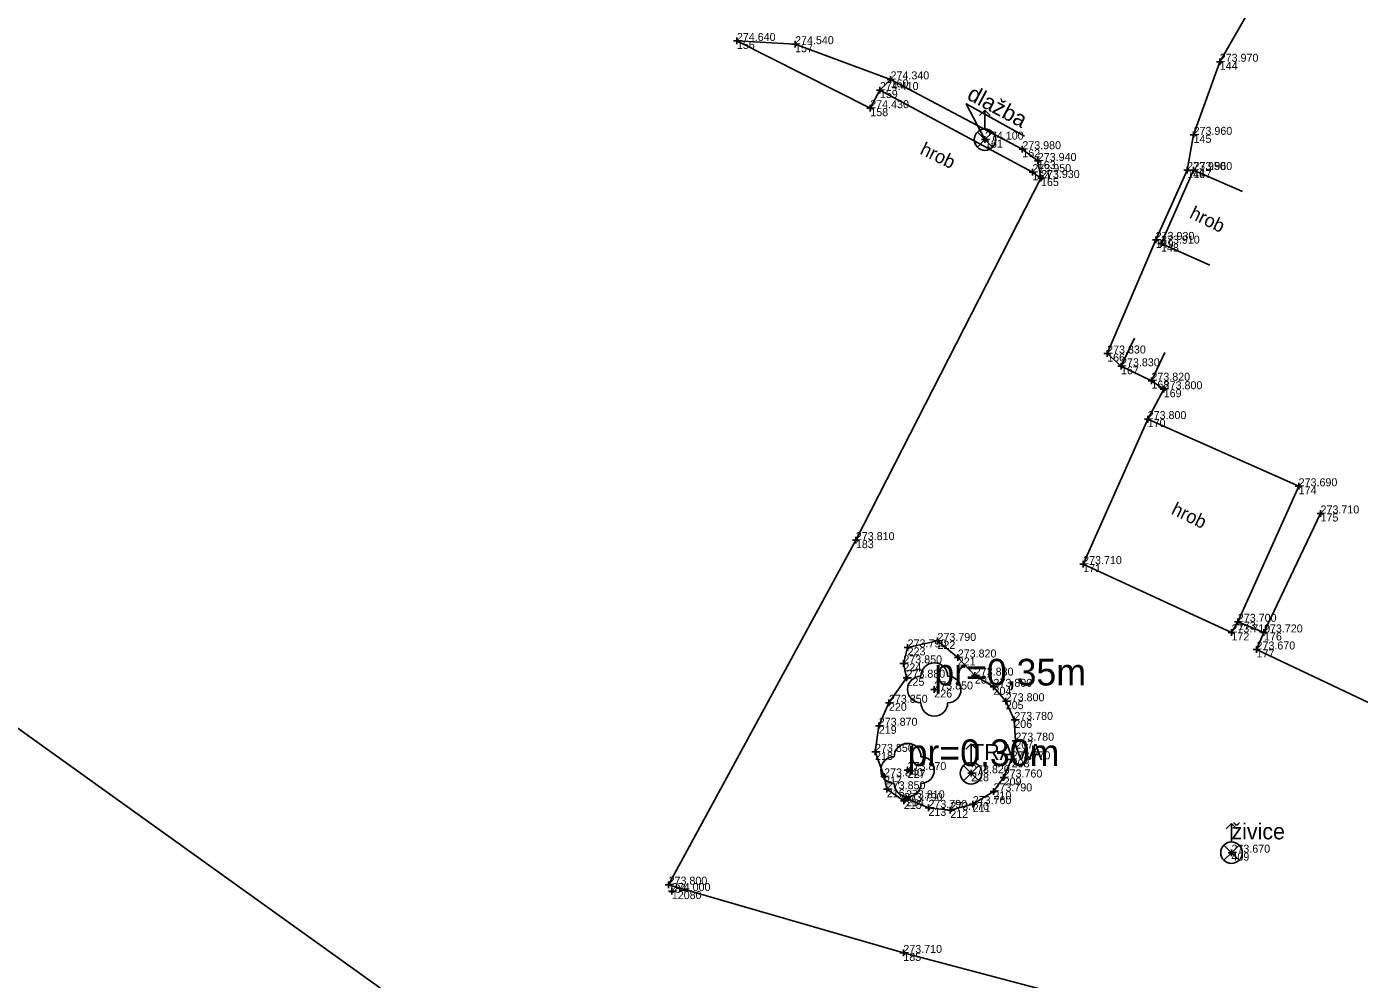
# Model space of a CAD drawing. Extents: x -776606 to -776076, y -974328 to -973875.
# Drawn here: x -776421.12 to -776396.14, y -974197.28 to -974179.42 of the extents above; entities that cross this region are included whole.
import ezdxf

# ---------------------------------------------------------------- set-up
doc = ezdxf.new("R2010")
doc.units = 0
for name, color, linetype in [('Body polohopisu', 7, 'Continuous'), ('Doplňkové značky', 7, 'Continuous'), ('Doplňující texty', 7, 'Continuous'), ('Hranice parcel', 7, 'Continuous'), ('Nezařazené objekty', 7, 'Continuous'), ('Ploty_opěrné zdi', 7, 'Continuous'), ('Rozhraní ploch', 7, 'Continuous'), ('Stromy_porost', 7, 'Continuous'), ('Výšky bodů', 7, 'Continuous'), ('Čísla bodů', 7, 'Continuous')]:
    doc.layers.add(name, color=color, linetype=linetype)

msp = doc.modelspace()

# ---------------------------------------------------------------- linework, layer by layer
at = {"layer": 'Body polohopisu'}
for p, q in [((-776407.81, -974179.69), (-776407.873, -974179.69)), ((-776407.81, -974179.69), (-776407.81, -974179.628)), ((-776407.81, -974179.69), (-776407.748, -974179.69)), ((-776407.81, -974179.69), (-776407.81, -974179.753)), ((-776406.72, -974179.75), (-776406.782, -974179.75)), ((-776406.72, -974179.75), (-776406.72, -974179.688)), ((-776406.72, -974179.75), (-776406.657, -974179.75)), ((-776406.72, -974179.75), (-776406.72, -974179.812)), ((-776398.76, -974180.08), (-776398.823, -974180.08)), ((-776398.76, -974180.08), (-776398.76, -974180.018)), ((-776398.76, -974180.08), (-776398.698, -974180.08)), ((-776398.76, -974180.08), (-776398.76, -974180.143)), ((-776405.13, -974180.61), (-776405.13, -974180.547)), ((-776404.93, -974180.41), (-776404.993, -974180.41)), ((-776404.93, -974180.41), (-776404.93, -974180.348)), ((-776404.93, -974180.41), (-776404.868, -974180.41)), ((-776404.93, -974180.41), (-776404.93, -974180.473)), ((-776405.13, -974180.61), (-776405.193, -974180.61)), ((-776405.13, -974180.61), (-776405.068, -974180.61)), ((-776405.13, -974180.61), (-776405.13, -974180.672)), ((-776405.31, -974180.95), (-776405.373, -974180.95)), ((-776405.31, -974180.95), (-776405.31, -974180.888)), ((-776405.31, -974180.95), (-776405.248, -974180.95)), ((-776405.31, -974180.95), (-776405.31, -974181.013)), ((-776403.16, -974181.54), (-776403.223, -974181.54)), ((-776403.16, -974181.54), (-776403.16, -974181.478)), ((-776403.16, -974181.54), (-776403.098, -974181.54)), ((-776403.16, -974181.54), (-776403.16, -974181.603)), ((-776399.25, -974181.45), (-776399.312, -974181.45)), ((-776399.25, -974181.45), (-776399.25, -974181.388)), ((-776399.25, -974181.45), (-776399.188, -974181.45)), ((-776399.25, -974181.45), (-776399.25, -974181.513)), ((-776402.46, -974181.72), (-776402.522, -974181.72)), ((-776402.46, -974181.72), (-776402.46, -974181.657)), ((-776402.46, -974181.72), (-776402.397, -974181.72)), ((-776402.46, -974181.72), (-776402.46, -974181.782)), ((-776402.17, -974181.94), (-776402.233, -974181.94)), ((-776402.17, -974181.94), (-776402.17, -974181.878)), ((-776402.17, -974181.94), (-776402.108, -974181.94)), ((-776402.17, -974181.94), (-776402.17, -974182.003)), ((-776399.37, -974182.11), (-776399.37, -974182.047)), ((-776399.25, -974182.11), (-776399.25, -974182.047)), ((-776402.27, -974182.15), (-776402.333, -974182.15)), ((-776402.27, -974182.15), (-776402.27, -974182.088)), ((-776402.27, -974182.15), (-776402.208, -974182.15)), ((-776402.27, -974182.15), (-776402.27, -974182.213)), ((-776402.11, -974182.26), (-776402.172, -974182.26)), ((-776402.11, -974182.26), (-776402.11, -974182.198)), ((-776402.11, -974182.26), (-776402.047, -974182.26)), ((-776402.11, -974182.26), (-776402.11, -974182.323)), ((-776399.37, -974182.11), (-776399.432, -974182.11)), ((-776399.37, -974182.11), (-776399.307, -974182.11)), ((-776399.37, -974182.11), (-776399.37, -974182.172)), ((-776399.25, -974182.11), (-776399.312, -974182.11)), ((-776399.25, -974182.11), (-776399.188, -974182.11)), ((-776399.25, -974182.11), (-776399.25, -974182.172)), ((-776399.96, -974183.42), (-776400.022, -974183.42)), ((-776399.96, -974183.42), (-776399.96, -974183.358)), ((-776399.96, -974183.42), (-776399.897, -974183.42)), ((-776399.96, -974183.42), (-776399.96, -974183.483)), ((-776399.86, -974183.49), (-776399.922, -974183.49)), ((-776399.86, -974183.49), (-776399.86, -974183.427)), ((-776399.86, -974183.49), (-776399.797, -974183.49)), ((-776399.86, -974183.49), (-776399.86, -974183.552)), ((-776400.87, -974185.55), (-776400.932, -974185.55)), ((-776400.87, -974185.55), (-776400.87, -974185.488)), ((-776400.87, -974185.55), (-776400.807, -974185.55)), ((-776400.87, -974185.55), (-776400.87, -974185.613)), ((-776400.61, -974185.79), (-776400.672, -974185.79)), ((-776400.61, -974185.79), (-776400.61, -974185.728)), ((-776400.61, -974185.79), (-776400.547, -974185.79)), ((-776400.61, -974185.79), (-776400.61, -974185.853)), ((-776400.04, -974186.06), (-776400.103, -974186.06)), ((-776400.04, -974186.06), (-776400.04, -974185.998)), ((-776400.04, -974186.06), (-776399.978, -974186.06)), ((-776400.04, -974186.06), (-776400.04, -974186.123)), ((-776399.81, -974186.22), (-776399.873, -974186.22)), ((-776399.81, -974186.22), (-776399.81, -974186.157)), ((-776399.81, -974186.22), (-776399.748, -974186.22)), ((-776399.81, -974186.22), (-776399.81, -974186.282)), ((-776400.11, -974186.78), (-776400.172, -974186.78)), ((-776400.11, -974186.78), (-776400.11, -974186.718)), ((-776400.11, -974186.78), (-776400.047, -974186.78)), ((-776400.11, -974186.78), (-776400.11, -974186.843)), ((-776397.28, -974188.04), (-776397.343, -974188.04)), ((-776397.28, -974188.04), (-776397.28, -974187.978)), ((-776397.28, -974188.04), (-776397.218, -974188.04)), ((-776397.28, -974188.04), (-776397.28, -974188.103)), ((-776396.87, -974188.55), (-776396.932, -974188.55)), ((-776396.87, -974188.55), (-776396.87, -974188.488)), ((-776396.87, -974188.55), (-776396.807, -974188.55)), ((-776396.87, -974188.55), (-776396.87, -974188.613)), ((-776405.58, -974189.05), (-776405.642, -974189.05)), ((-776405.58, -974189.05), (-776405.58, -974188.988)), ((-776405.58, -974189.05), (-776405.517, -974189.05)), ((-776405.58, -974189.05), (-776405.58, -974189.113)), ((-776401.32, -974189.5), (-776401.383, -974189.5)), ((-776401.32, -974189.5), (-776401.32, -974189.438)), ((-776401.32, -974189.5), (-776401.258, -974189.5)), ((-776401.32, -974189.5), (-776401.32, -974189.562)), ((-776398.42, -974190.58), (-776398.42, -974190.518)), ((-776398.54, -974190.78), (-776398.603, -974190.78)), ((-776398.54, -974190.78), (-776398.54, -974190.718)), ((-776398.54, -974190.78), (-776398.478, -974190.78)), ((-776398.54, -974190.78), (-776398.54, -974190.843)), ((-776398.42, -974190.58), (-776398.483, -974190.58)), ((-776398.42, -974190.58), (-776398.358, -974190.58)), ((-776398.42, -974190.58), (-776398.42, -974190.643)), ((-776397.93, -974190.78), (-776397.993, -974190.78)), ((-776397.93, -974190.78), (-776397.93, -974190.718)), ((-776397.93, -974190.78), (-776397.868, -974190.78)), ((-776397.93, -974190.78), (-776397.93, -974190.843)), ((-776404.61, -974191.06), (-776404.672, -974191.06)), ((-776404.61, -974191.06), (-776404.61, -974190.998)), ((-776404.61, -974191.06), (-776404.547, -974191.06)), ((-776404.61, -974191.06), (-776404.61, -974191.123)), ((-776404.05, -974190.94), (-776404.113, -974190.94)), ((-776404.05, -974190.94), (-776404.05, -974190.878)), ((-776404.05, -974190.94), (-776403.988, -974190.94)), ((-776404.05, -974190.94), (-776404.05, -974191.003)), ((-776398.07, -974191.1), (-776398.07, -974191.037)), ((-776404.69, -974191.36), (-776404.69, -974191.297)), ((-776403.67, -974191.25), (-776403.733, -974191.25)), ((-776403.67, -974191.25), (-776403.67, -974191.188)), ((-776403.67, -974191.25), (-776403.608, -974191.25)), ((-776403.67, -974191.25), (-776403.67, -974191.312)), ((-776398.07, -974191.1), (-776398.133, -974191.1)), ((-776398.07, -974191.1), (-776398.008, -974191.1)), ((-776398.07, -974191.1), (-776398.07, -974191.162)), ((-776404.69, -974191.36), (-776404.753, -974191.36)), ((-776404.69, -974191.36), (-776404.628, -974191.36)), ((-776404.69, -974191.36), (-776404.69, -974191.422)), ((-776404.63, -974191.63), (-776404.63, -974191.568)), ((-776403.35, -974191.59), (-776403.35, -974191.527)), ((-776404.63, -974191.63), (-776404.693, -974191.63)), ((-776404.63, -974191.63), (-776404.568, -974191.63)), ((-776404.63, -974191.63), (-776404.63, -974191.693)), ((-776404.11, -974191.85), (-776404.11, -974191.787)), ((-776403.35, -974191.59), (-776403.412, -974191.59)), ((-776403.35, -974191.59), (-776403.287, -974191.59)), ((-776403.35, -974191.59), (-776403.35, -974191.652)), ((-776403, -974191.8), (-776403.062, -974191.8)), ((-776403, -974191.8), (-776403, -974191.738)), ((-776403, -974191.8), (-776402.938, -974191.8)), ((-776403, -974191.8), (-776403, -974191.863)), ((-776404.96, -974192.1), (-776404.96, -974192.037)), ((-776404.11, -974191.85), (-776404.172, -974191.85)), ((-776404.11, -974191.85), (-776404.047, -974191.85)), ((-776404.11, -974191.85), (-776404.11, -974191.912)), ((-776402.77, -974192.07), (-776402.833, -974192.07)), ((-776402.77, -974192.07), (-776402.77, -974192.008)), ((-776402.77, -974192.07), (-776402.708, -974192.07)), ((-776402.77, -974192.07), (-776402.77, -974192.133)), ((-776404.96, -974192.1), (-776405.022, -974192.1)), ((-776404.96, -974192.1), (-776404.897, -974192.1)), ((-776404.96, -974192.1), (-776404.96, -974192.162)), ((-776405.15, -974192.53), (-776405.213, -974192.53)), ((-776405.15, -974192.53), (-776405.15, -974192.468)), ((-776405.15, -974192.53), (-776405.088, -974192.53)), ((-776405.15, -974192.53), (-776405.15, -974192.593)), ((-776402.61, -974192.42), (-776402.672, -974192.42)), ((-776402.61, -974192.42), (-776402.61, -974192.358)), ((-776402.61, -974192.42), (-776402.547, -974192.42)), ((-776402.61, -974192.42), (-776402.61, -974192.483)), ((-776402.59, -974192.81), (-776402.652, -974192.81)), ((-776402.59, -974192.81), (-776402.59, -974192.748)), ((-776402.59, -974192.81), (-776402.527, -974192.81)), ((-776402.59, -974192.81), (-776402.59, -974192.873)), ((-776405.22, -974193.02), (-776405.282, -974193.02)), ((-776405.22, -974193.02), (-776405.22, -974192.958)), ((-776405.22, -974193.02), (-776405.157, -974193.02)), ((-776405.22, -974193.02), (-776405.22, -974193.083)), ((-776404.61, -974193.36), (-776404.61, -974193.297)), ((-776402.66, -974193.16), (-776402.723, -974193.16)), ((-776402.66, -974193.16), (-776402.66, -974193.098)), ((-776402.66, -974193.16), (-776402.598, -974193.16)), ((-776402.66, -974193.16), (-776402.66, -974193.223)), ((-776405.05, -974193.48), (-776405.113, -974193.48)), ((-776405.05, -974193.48), (-776405.05, -974193.417)), ((-776405.05, -974193.48), (-776404.988, -974193.48)), ((-776405.05, -974193.48), (-776405.05, -974193.542)), ((-776404.61, -974193.36), (-776404.672, -974193.36)), ((-776404.61, -974193.36), (-776404.547, -974193.36)), ((-776404.61, -974193.36), (-776404.61, -974193.422)), ((-776403.42, -974193.42), (-776403.483, -974193.42)), ((-776403.42, -974193.42), (-776403.42, -974193.358)), ((-776403.42, -974193.42), (-776403.358, -974193.42)), ((-776403.42, -974193.42), (-776403.42, -974193.483)), ((-776402.81, -974193.5), (-776402.873, -974193.5)), ((-776402.81, -974193.5), (-776402.81, -974193.438)), ((-776402.81, -974193.5), (-776402.748, -974193.5)), ((-776402.81, -974193.5), (-776402.81, -974193.562)), ((-776405, -974193.72), (-776405.062, -974193.72)), ((-776405, -974193.72), (-776405, -974193.657)), ((-776405, -974193.72), (-776404.938, -974193.72)), ((-776405, -974193.72), (-776405, -974193.782)), ((-776403, -974193.76), (-776403.062, -974193.76)), ((-776403, -974193.76), (-776403, -974193.698)), ((-776403, -974193.76), (-776402.938, -974193.76)), ((-776403, -974193.76), (-776403, -974193.823)), ((-776404.68, -974193.94), (-776404.743, -974193.94)), ((-776404.64, -974193.89), (-776404.703, -974193.89)), ((-776404.68, -974193.94), (-776404.68, -974193.878)), ((-776404.68, -974193.94), (-776404.618, -974193.94)), ((-776404.68, -974193.94), (-776404.68, -974194.003)), ((-776404.64, -974193.89), (-776404.64, -974193.828)), ((-776404.64, -974193.89), (-776404.578, -974193.89)), ((-776404.64, -974193.89), (-776404.64, -974193.953)), ((-776404.22, -974194.07), (-776404.282, -974194.07)), ((-776404.22, -974194.07), (-776404.22, -974194.008)), ((-776404.22, -974194.07), (-776404.157, -974194.07)), ((-776404.22, -974194.07), (-776404.22, -974194.133)), ((-776403.81, -974194.11), (-776403.81, -974194.047)), ((-776403.39, -974194), (-776403.453, -974194)), ((-776403.39, -974194), (-776403.39, -974193.938)), ((-776403.39, -974194), (-776403.328, -974194)), ((-776403.39, -974194), (-776403.39, -974194.062)), ((-776403.81, -974194.11), (-776403.873, -974194.11)), ((-776403.81, -974194.11), (-776403.748, -974194.11)), ((-776403.81, -974194.11), (-776403.81, -974194.172)), ((-776398.54, -974194.91), (-776398.603, -974194.91)), ((-776398.54, -974194.91), (-776398.54, -974194.848)), ((-776398.54, -974194.91), (-776398.478, -974194.91)), ((-776398.54, -974194.91), (-776398.54, -974194.973)), ((-776409.09, -974195.51), (-776409.152, -974195.51)), ((-776409.09, -974195.51), (-776409.09, -974195.448)), ((-776409.09, -974195.51), (-776409.027, -974195.51)), ((-776409.09, -974195.51), (-776409.09, -974195.573)), ((-776409.03, -974195.63), (-776409.03, -974195.568)), ((-776409.03, -974195.63), (-776409.093, -974195.63)), ((-776409.03, -974195.63), (-776408.968, -974195.63)), ((-776409.03, -974195.63), (-776409.03, -974195.693)), ((-776404.69, -974196.79), (-776404.753, -974196.79)), ((-776404.69, -974196.79), (-776404.69, -974196.728)), ((-776404.69, -974196.79), (-776404.628, -974196.79)), ((-776404.69, -974196.79), (-776404.69, -974196.853))]:
    msp.add_line(p, q, dxfattribs=at)
at = {"layer": 'Doplňkové značky'}
for p, q in [((-776403.16, -974180.99), (-776403.26, -974181.09)), ((-776403.16, -974181.338), (-776403.16, -974180.99)), ((-776403.16, -974180.99), (-776403.06, -974181.09)), ((-776403.16, -974181.54), (-776403.302, -974181.397)), ((-776403.16, -974181.54), (-776403.302, -974181.682)), ((-776403.16, -974181.54), (-776403.017, -974181.397)), ((-776403.16, -974181.54), (-776403.16, -974181.54)), ((-776403.16, -974181.54), (-776403.017, -974181.682)), ((-776403.42, -974192.87), (-776403.52, -974192.97)), ((-776403.42, -974193.218), (-776403.42, -974192.87)), ((-776403.42, -974192.87), (-776403.32, -974192.97)), ((-776403.42, -974193.42), (-776403.562, -974193.277)), ((-776403.42, -974193.42), (-776403.277, -974193.277)), ((-776403.42, -974193.42), (-776403.562, -974193.562)), ((-776403.42, -974193.42), (-776403.42, -974193.42)), ((-776403.42, -974193.42), (-776403.277, -974193.562)), ((-776398.54, -974194.36), (-776398.64, -974194.46)), ((-776398.54, -974194.708), (-776398.54, -974194.36)), ((-776398.54, -974194.36), (-776398.44, -974194.46)), ((-776398.54, -974194.91), (-776398.682, -974194.768)), ((-776398.54, -974194.91), (-776398.397, -974194.768)), ((-776398.54, -974194.91), (-776398.682, -974195.052)), ((-776398.54, -974194.91), (-776398.54, -974194.91)), ((-776398.54, -974194.91), (-776398.397, -974195.052))]:
    msp.add_line(p, q, dxfattribs=at)
for centre in [(-776403.16, -974181.54), (-776403.42, -974193.42), (-776398.54, -974194.91)]:
    msp.add_circle(centre, 0.202, dxfattribs=at)
at = {"layer": 'Doplňující texty'}
msp.add_lwpolyline([(-776403.16, -974181.54), (-776403.51, -974180.868), (-776402.419, -974181.473)], dxfattribs=at)
at = {"layer": 'Hranice parcel'}
msp.add_line((-776424.22, -974190.48), (-776414.02, -974197.79), dxfattribs=at)
at = {"layer": 'Nezařazené objekty'}
for points in [[(-776405.05, -974193.48), (-776405.22, -974193.02), (-776405.15, -974192.53), (-776404.96, -974192.1), (-776404.63, -974191.63)], [(-776403.35, -974191.59), (-776403, -974191.8), (-776402.77, -974192.07), (-776402.61, -974192.42), (-776402.59, -974192.81), (-776402.66, -974193.16), (-776402.81, -974193.5), (-776403, -974193.76), (-776403.39, -974194), (-776403.81, -974194.11), (-776404.22, -974194.07), (-776404.64, -974193.89), (-776404.68, -974193.94), (-776405, -974193.72)]]:
    msp.add_lwpolyline(points, dxfattribs=at)
at = {"layer": 'Ploty_opěrné zdi'}
msp.add_lwpolyline([(-776405.31, -974180.95), (-776405.13, -974180.61), (-776402.27, -974182.15)], dxfattribs=at)
at = {"layer": 'Rozhraní ploch'}
for points in [[(-776397.41, -974177.93), (-776398.03, -974178.81), (-776398.76, -974180.08), (-776399.25, -974181.45), (-776399.37, -974182.11), (-776399.96, -974183.42), (-776400.87, -974185.55), (-776400.61, -974185.79)], [(-776407.81, -974179.69), (-776406.72, -974179.75), (-776404.93, -974180.41), (-776402.46, -974181.72), (-776402.17, -974181.94), (-776402.11, -974182.26)], [(-776407.81, -974179.69), (-776405.31, -974180.95)], [(-776405.13, -974180.61), (-776404.93, -974180.41)], [(-776402.27, -974182.15), (-776402.11, -974182.26), (-776405.58, -974189.05), (-776409.09, -974195.51), (-776404.69, -974196.79), (-776400.93, -974197.78), (-776396.03, -974199.17), (-776396.07, -974199.37), (-776395.22, -974199.6), (-776395.17, -974199.4), (-776393.77, -974199.81), (-776393.73, -974199.63), (-776391.65, -974200.17), (-776391.69, -974200.35), (-776390.84, -974200.57), (-776390.78, -974200.41), (-776385.82, -974201.79), (-776382.94, -974202.63), (-776383.306, -974203.936)], [(-776398.335, -974182.514), (-776399.25, -974182.11), (-776399.86, -974183.49), (-776398.945, -974183.894)], [(-776400.359, -974185.26), (-776400.61, -974185.79), (-776400.04, -974186.06), (-776399.789, -974185.53)], [(-776400.04, -974186.06), (-776399.81, -974186.22), (-776400.11, -974186.78)], [(-776397.28, -974188.04), (-776400.11, -974186.78), (-776401.32, -974189.5), (-776398.54, -974190.78), (-776398.42, -974190.58), (-776397.28, -974188.04)], [(-776396.87, -974188.55), (-776397.93, -974190.78), (-776398.07, -974191.1), (-776394.63, -974192.73), (-776391.17, -974194.38), (-776387.73, -974195.98), (-776387.69, -974195.93), (-776384.31, -974197.58), (-776380.77, -974199.14), (-776379.53, -974196.48)], [(-776398.42, -974190.58), (-776397.93, -974190.78)], [(-776403.35, -974191.59), (-776403.67, -974191.25), (-776404.05, -974190.94), (-776404.61, -974191.06), (-776404.69, -974191.36), (-776404.63, -974191.63)], [(-776405, -974193.72), (-776405.05, -974193.48)]]:
    msp.add_lwpolyline(points, dxfattribs=at)
at = {"layer": 'Stromy_porost'}
for centre in [(-776404.11, -974191.85), (-776404.61, -974193.36)]:
    msp.add_circle(centre, 0.00025, dxfattribs=at)
for centre, start, end in [((-776404.11, -974191.6), 0, 180), ((-776404.36, -974191.85), 90, 270), ((-776403.86, -974191.85), 270, 90), ((-776404.11, -974192.1), 180, 360), ((-776404.61, -974193.11), 0, 180), ((-776404.86, -974193.36), 90, 270), ((-776404.36, -974193.36), 270, 90), ((-776404.61, -974193.61), 180, 360)]:
    msp.add_arc(centre, 0.25, start, end, dxfattribs=at)

# ---------------------------------------------------------------- texts
at = {"layer": 'Doplňující texty'}
for s, height, rotation, p in [('dlažba', 0.3, 332.0601, (-776403.517, -974180.772)), ('hrob', 0.25, 333.9465, (-776404.396, -974181.801)), ('hrob', 0.25, 333.9465, (-776399.344, -974182.999)), ('hrob', 0.25, 333.9465, (-776399.686, -974188.55))]:
    msp.add_text(s, height=height, rotation=rotation, dxfattribs=at).set_placement(p)
for s, height, p in [('pr=0,35m', 0.5, (-776404.11, -974191.775)), ('pr=0,30m', 0.5, (-776404.61, -974193.285)), ('TRAVA', 0.3, (-776403.42, -974193.17)), ('živice', 0.3, (-776398.54, -974194.66))]:
    msp.add_text(s, height=height, dxfattribs=at).set_placement(p)
at = {"layer": 'Výšky bodů'}
for s, p in [('274.640', (-776407.81, -974179.69)), ('274.540', (-776406.72, -974179.75)), ('273.970', (-776398.76, -974180.08)), ('274.340', (-776404.93, -974180.41)), ('274.410', (-776405.13, -974180.61)), ('274.430', (-776405.31, -974180.95)), ('273.960', (-776399.25, -974181.45)), ('274.100', (-776403.16, -974181.54)), ('273.980', (-776402.46, -974181.72)), ('273.940', (-776402.17, -974181.94)), ('273.950', (-776402.27, -974182.15)), ('273.950', (-776399.37, -974182.11)), ('273.960', (-776399.25, -974182.11)), ('273.930', (-776402.11, -974182.26)), ('273.930', (-776399.96, -974183.42)), ('273.910', (-776399.86, -974183.49)), ('273.830', (-776400.87, -974185.55)), ('273.830', (-776400.61, -974185.79)), ('273.820', (-776400.04, -974186.06)), ('273.800', (-776399.81, -974186.22)), ('273.800', (-776400.11, -974186.78)), ('273.690', (-776397.28, -974188.04)), ('273.710', (-776396.87, -974188.55)), ('273.810', (-776405.58, -974189.05)), ('273.710', (-776401.32, -974189.5)), ('273.700', (-776398.42, -974190.58)), ('273.790', (-776404.05, -974190.94)), ('273.710', (-776398.54, -974190.78)), ('273.720', (-776397.93, -974190.78)), ('273.790', (-776404.61, -974191.06)), ('273.670', (-776398.07, -974191.1)), ('273.850', (-776404.69, -974191.36)), ('273.820', (-776403.67, -974191.25)), ('273.880', (-776404.63, -974191.63)), ('273.880', (-776403.35, -974191.59)), ('273.850', (-776404.11, -974191.85)), ('273.800', (-776403, -974191.8)), ('273.850', (-776404.96, -974192.1)), ('273.800', (-776402.77, -974192.07)), ('273.780', (-776402.61, -974192.42)), ('273.870', (-776405.15, -974192.53)), ('273.780', (-776402.59, -974192.81)), ('273.850', (-776405.22, -974193.02)), ('273.770', (-776402.66, -974193.16)), ('273.870', (-776404.61, -974193.36)), ('273.820', (-776403.42, -974193.42)), ('273.840', (-776405.05, -974193.48)), ('273.850', (-776405, -974193.72)), ('273.760', (-776402.81, -974193.5)), ('273.790', (-776404.68, -974193.94)), ('273.810', (-776404.64, -974193.89)), ('273.790', (-776403, -974193.76)), ('273.790', (-776404.22, -974194.07)), ('273.770', (-776403.81, -974194.11)), ('273.760', (-776403.39, -974194)), ('273.670', (-776398.54, -974194.91)), ('273.800', (-776409.09, -974195.51)), ('274.000', (-776409.03, -974195.63)), ('273.710', (-776404.69, -974196.79))]:
    msp.add_text(s, height=0.15, dxfattribs=at).set_placement(p)
at = {"layer": 'Čísla bodů'}
for s, p in [('156', (-776407.81, -974179.84)), ('157', (-776406.72, -974179.9)), ('144', (-776398.76, -974180.23)), ('160', (-776404.93, -974180.56)), ('159', (-776405.13, -974180.76)), ('158', (-776405.31, -974181.1)), ('161', (-776403.16, -974181.69)), ('145', (-776399.25, -974181.6)), ('162', (-776402.46, -974181.87)), ('163', (-776402.17, -974182.09)), ('164', (-776402.27, -974182.3)), ('165', (-776402.11, -974182.41)), ('146', (-776399.37, -974182.26)), ('147', (-776399.25, -974182.26)), ('149', (-776399.96, -974183.57)), ('148', (-776399.86, -974183.64)), ('166', (-776400.87, -974185.7)), ('167', (-776400.61, -974185.94)), ('168', (-776400.04, -974186.21)), ('169', (-776399.81, -974186.37)), ('170', (-776400.11, -974186.93)), ('174', (-776397.28, -974188.19)), ('175', (-776396.87, -974188.7)), ('183', (-776405.58, -974189.2)), ('171', (-776401.32, -974189.65)), ('172', (-776398.54, -974190.93)), ('173', (-776398.42, -974190.73)), ('176', (-776397.93, -974190.93)), ('223', (-776404.61, -974191.21)), ('222', (-776404.05, -974191.09)), ('221', (-776403.67, -974191.4)), ('177', (-776398.07, -974191.25)), ('224', (-776404.69, -974191.51)), ('225', (-776404.63, -974191.78)), ('203', (-776403.35, -974191.74)), ('204', (-776403, -974191.95)), ('226', (-776404.11, -974192)), ('205', (-776402.77, -974192.22)), ('220', (-776404.96, -974192.25)), ('219', (-776405.15, -974192.68)), ('206', (-776402.61, -974192.57)), ('207', (-776402.59, -974192.96)), ('218', (-776405.22, -974193.17)), ('208', (-776402.66, -974193.31)), ('217', (-776405.05, -974193.63)), ('227', (-776404.61, -974193.51)), ('228', (-776403.42, -974193.57)), ('209', (-776402.81, -974193.65)), ('216', (-776405, -974193.87)), ('210', (-776403, -974193.91)), ('215', (-776404.68, -974194.09)), ('214', (-776404.64, -974194.04)), ('213', (-776404.22, -974194.22)), ('211', (-776403.39, -974194.15)), ('212', (-776403.81, -974194.26)), ('409', (-776398.54, -974195.06)), ('184', (-776409.09, -974195.66)), ('12080', (-776409.03, -974195.78)), ('185', (-776404.69, -974196.94))]:
    msp.add_text(s, height=0.15, dxfattribs=at).set_placement(p)

doc.saveas('drawing.dxf')
